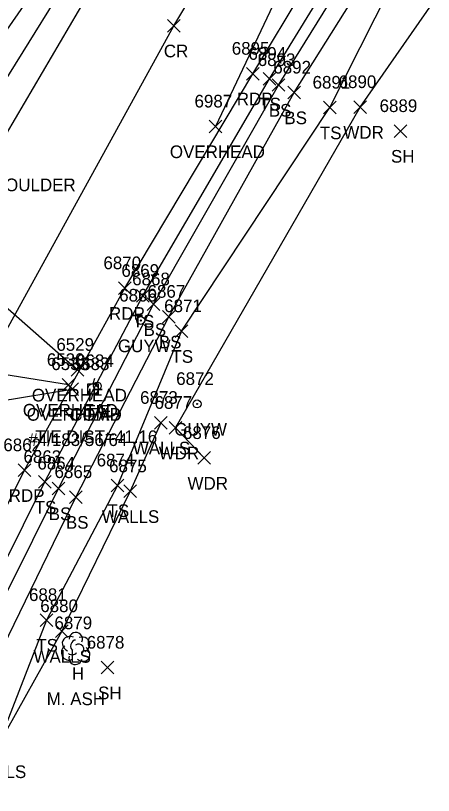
# Model space of a CAD drawing. Extents: x 1611797 to 1633212, y 298978 to 305475.
# Drawn here: x 1623791 to 1623857, y 303824.4 to 303947.6 of the extents above; entities that cross this region are included whole.
import ezdxf

# ---------------------------------------------------------------- set-up
doc = ezdxf.new("R2010")
doc.units = 0
for name, color, linetype in [('C_A', 7, 'Continuous'), ('C_C', 7, 'Continuous'), ('C_I', 7, 'Continuous'), ('CBP', 7, 'Continuous'), ('L_A', 7, 'Continuous'), ('L_C', 7, 'Continuous'), ('L_I', 7, 'Continuous'), ('L_TIC', 7, 'Continuous'), ('LAWA', 7, 'Continuous'), ('LELB', 7, 'Continuous'), ('LTD', 7, 'Continuous'), ('LWS', 7, 'Continuous'), ('P_A', 7, 'Continuous'), ('P_I', 7, 'Continuous'), ('P_TIC', 7, 'Continuous'), ('PET', 7, 'Continuous'), ('PRC', 7, 'Continuous'), ('U_A', 7, 'Continuous'), ('U_C', 7, 'Continuous'), ('U_I', 7, 'Continuous'), ('U_TIC', 7, 'Continuous'), ('UCO', 7, 'Continuous'), ('UP', 7, 'Continuous'), ('UPGW', 7, 'Continuous')]:
    doc.layers.add(name, color=color, linetype=linetype)

msp = doc.modelspace()

# ---------------------------------------------------------------- linework, layer by layer
at = {"layer": 'CBP'}
for radius in [0.625, 0.0833]:
    msp.add_circle((1623803.91, 303889.04), radius, dxfattribs=at)
at = {"layer": 'L_TIC'}
for points in [[(1623830.07, 303936.59), (1623832.07, 303938.59)], [(1623832.07, 303936.59), (1623830.07, 303938.59)], [(1623831.53, 303935.61), (1623833.53, 303937.61)], [(1623833.53, 303935.61), (1623831.53, 303937.61)], [(1623834, 303934.42), (1623836, 303936.42)], [(1623836, 303934.42), (1623834, 303936.42)], [(1623839.63, 303932.04), (1623841.63, 303934.04)], [(1623841.63, 303932.04), (1623839.63, 303934.04)], [(1623839.63, 303932.04), (1623841.63, 303934.04)], [(1623841.63, 303932.04), (1623839.63, 303934.04)], [(1623844.39, 303932.13), (1623846.39, 303934.13)], [(1623846.39, 303932.13), (1623844.39, 303934.13)], [(1623850.79, 303928.34), (1623852.79, 303930.34)], [(1623852.79, 303928.34), (1623850.79, 303930.34)], [(1623810.07, 303902.3), (1623812.07, 303904.3)], [(1623812.07, 303902.3), (1623810.07, 303904.3)], [(1623811.76, 303900.96), (1623813.76, 303902.96)], [(1623813.76, 303900.96), (1623811.76, 303902.96)], [(1623814.19, 303899), (1623816.19, 303901)], [(1623816.19, 303899), (1623814.19, 303901)], [(1623816.2, 303896.72), (1623818.2, 303898.72)], [(1623818.2, 303896.72), (1623816.2, 303898.72)], [(1623816.2, 303896.72), (1623818.2, 303898.72)], [(1623818.2, 303896.72), (1623816.2, 303898.72)], [(1623812.96, 303882.24), (1623814.96, 303884.24)], [(1623814.96, 303882.24), (1623812.96, 303884.24)], [(1623815.25, 303881.45), (1623817.25, 303883.45)], [(1623817.25, 303881.45), (1623815.25, 303883.45)], [(1623819.79, 303876.68), (1623821.79, 303878.68)], [(1623821.79, 303876.68), (1623819.79, 303878.68)], [(1623794.61, 303872.89), (1623796.61, 303874.89)], [(1623796.61, 303872.89), (1623794.61, 303874.89)], [(1623796.8, 303871.86), (1623798.8, 303873.86)], [(1623798.8, 303871.86), (1623796.8, 303873.86)], [(1623806.11, 303872.35), (1623808.11, 303874.35)], [(1623808.11, 303872.35), (1623806.11, 303874.35)], [(1623799.51, 303870.51), (1623801.51, 303872.51)], [(1623801.51, 303870.51), (1623799.51, 303872.51)], [(1623808.08, 303871.42), (1623810.08, 303873.42)], [(1623810.08, 303871.42), (1623808.08, 303873.42)], [(1623794.86, 303851.08), (1623796.86, 303853.08)], [(1623796.86, 303851.08), (1623794.86, 303853.08)], [(1623797.29, 303849.33), (1623799.29, 303851.33)], [(1623799.29, 303849.33), (1623797.29, 303851.33)], [(1623804.54, 303843.56), (1623806.54, 303845.56)], [(1623806.54, 303843.56), (1623804.54, 303845.56)]]:
    msp.add_lwpolyline(points, dxfattribs=at)
at = {"layer": 'LAWA'}
msp.add_lwpolyline([(1623820.79, 303877.68), (1623816.25, 303882.45), (1623845.39, 303933.13), (1623868.52, 303966.33), (1623895.88, 304001.62), (1623916.89, 304037.42), (1623938.51, 304074.19), (1623964.42, 304107.21), (1624004.64, 304144.93), (1624031.16, 304170.25), (1624074.89, 304204.59), (1624093.25, 304225.45), (1624128.84, 304248.67), (1624153.26, 304270.75), (1624186.93, 304294.55), (1624240.75, 304330.36)], dxfattribs=at)
at = {"layer": 'LELB'}
for points in [[(1623740.23, 303740.54), (1623735.95, 303738.13), (1623733.04, 303738.73), (1623730.26, 303741.26), (1623736.66, 303755.3), (1623756.47, 303795.98), (1623775.32, 303833.05), (1623795.61, 303873.89), (1623811.07, 303903.3), (1623831.07, 303937.59), (1623850.6, 303969.47), (1623881.4, 304014.8), (1623901.24, 304044.35), (1623930, 304082.68), (1623952.95, 304110.39), (1623992.55, 304153.19), (1624020.81, 304180.67), (1624058.38, 304214.54), (1624070.13, 304221.5)], [(1623733.78, 303740.47), (1623738.51, 303754.96), (1623759.12, 303794.85), (1623777.54, 303832.17), (1623797.8, 303872.86), (1623812.76, 303901.96), (1623832.53, 303936.61), (1623852.45, 303968.82), (1623883.01, 304013.7), (1623903, 304043.14), (1623931.54, 304080.8), (1623954.14, 304109.34), (1623993.44, 304152.2), (1624022.26, 304179.45), (1624060.69, 304212.27), (1624070.13, 304220.57)], [(1623733.78, 303740.47), (1623735.41, 303740.12), (1623741.31, 303753.52), (1623763.42, 303793.2), (1623780.16, 303829.64), (1623800.51, 303871.51), (1623815.19, 303900), (1623835, 303935.42), (1623854.96, 303967.29), (1623885.08, 304011.89), (1623905.91, 304041.32), (1623933.42, 304079.65), (1623956.31, 304107.74), (1623995.39, 304150.94), (1624023.82, 304177.46), (1624061.85, 304211.18), (1624071.01, 304219.63), (1624070.13, 304220.57)], [(1623840.63, 303933.04), (1623857.36, 303966.24), (1623887.8, 304009.35), (1623908, 304039.91), (1623936.29, 304076.6), (1623958.73, 304105.76), (1623997.87, 304149.47), (1624026.32, 304175.43), (1624063.15, 304209.38), (1624073.81, 304217.48), (1624072.56, 304218.74)], [(1623716.05, 303912.02), (1623732.35, 303913.81), (1623759.04, 303912.24), (1623771.78, 303913.97), (1623774.93, 303915.99), (1623779.73, 303921.83), (1623800.29, 303954.97), (1623820.51, 303988.09), (1623840.34, 304020.02), (1623836.12, 304025.99), (1623832.01, 304025.34)], [(1623817.2, 303897.72), (1623840.63, 303933.04)], [(1623817.2, 303897.72), (1623807.11, 303873.35), (1623795.86, 303852.08), (1623788.08, 303832.11), (1623776.41, 303807.67), (1623761.8, 303779.72), (1623754.87, 303764.43)]]:
    msp.add_lwpolyline(points, dxfattribs=at)
at = {"layer": 'LTD'}
msp.add_line((1623800.46, 303847.63), (1623800.46, 303847.63), dxfattribs=at)
msp.add_line((1623800.46, 303847.63), (1623800.46, 303847.63), dxfattribs=at)
msp.add_arc((1623800.51, 303849.06), 1.05, 335.5272, 180.9563, dxfattribs=at)
for centre, major_axis, ratio, start_param, end_param in [((1623799.67, 303848.29), (1.21, -0.51), 0.895232, 1.570796, 4.712389), ((1623801.5, 303848.21), (-1.14, -0.48), 0.949671, 1.570796, 4.712389), ((1623799.38, 303846.92), (0.58, -1.04), 0.959034, 3.141593, 6.283185), ((1623800.25, 303848.09), (-0.208, -0.792), 0.645439, 3.141593, 6.283185), ((1623800.96, 303847.46), (-0.5, 0.667), 0.989748, 3.141593, 6.283185), ((1623800, 303846.88), (-0.625, -0.083), 0.423636, 0, 3.141593), ((1623801.46, 303846.8), (-1.09, 0.79), 0.841452, 1.570796, 4.712389), ((1623800.46, 303846.13), (0.26, 1.06), 0.942809, 1.570796, 4.712389)]:
    msp.add_ellipse(centre, major_axis=major_axis, ratio=ratio, start_param=start_param, end_param=end_param, dxfattribs=at)
at = {"layer": 'LWS'}
for points in [[(1623717.19, 303914.78), (1623732.04, 303916.68), (1623760.06, 303916.18), (1623770.53, 303917.84), (1623797.52, 303956.71), (1623816.42, 303989.59), (1623837.84, 304021.99)], [(1623813.96, 303883.24), (1623809.08, 303872.42), (1623798.29, 303850.33), (1623788.08, 303832.11)]]:
    msp.add_lwpolyline(points, dxfattribs=at)
at = {"layer": 'P_TIC'}
for points in [[(1623814.97, 303944.98), (1623816.97, 303946.98)], [(1623816.97, 303944.98), (1623814.97, 303946.98)], [(1623827.44, 303937.4), (1623829.44, 303939.4)], [(1623829.44, 303937.4), (1623827.44, 303939.4)], [(1623807.26, 303903.51), (1623809.26, 303905.51)], [(1623809.26, 303903.51), (1623807.26, 303905.51)], [(1623791.43, 303874.75), (1623793.43, 303876.75)], [(1623793.43, 303874.75), (1623791.43, 303876.75)]]:
    msp.add_lwpolyline(points, dxfattribs=at)
at = {"layer": 'PET'}
for points in [[(1623734.72, 303818.72), (1623741.35, 303832.79), (1623751.88, 303855.21), (1623768.06, 303888.23), (1623783.81, 303919.21), (1623803.8, 303953.17), (1623823.4, 303986.78), (1623844.63, 304021.43), (1623861.98, 304047.29), (1623874.41, 304064.9), (1623903.88, 304103.57), (1623926.42, 304130.92), (1623968.84, 304177.26), (1623998.66, 304205.49), (1624036.82, 304239.77), (1624084.71, 304279.03), (1624112.56, 304299.92), (1624120.23, 304305.61), (1624165.06, 304338.25), (1624214.6, 304372.95), (1624258.69, 304401.17)], [(1623753.98, 303796.37), (1623772.12, 303834.51), (1623792.43, 303875.75), (1623808.26, 303904.51), (1623828.44, 303938.4), (1623847.99, 303970.88), (1623878.6, 304016.89), (1623898.4, 304046.12), (1623927.58, 304084.75), (1623950.31, 304112.67), (1623990.12, 304155.59), (1624018.08, 304183.31), (1624056.52, 304216.58), (1624078.27, 304234.86), (1624102.63, 304254.08), (1624138.53, 304281.62), (1624179.36, 304312.24), (1624229.96, 304347.62)]]:
    msp.add_lwpolyline(points, dxfattribs=at)
at = {"layer": 'PRC'}
msp.add_lwpolyline([(1623741.55, 303802.02), (1623760.52, 303841.05), (1623780.51, 303881.51), (1623815.97, 303945.98), (1623835.49, 303978.53), (1623866.25, 304025.48), (1623886.62, 304054.99), (1623916.18, 304093.56), (1623939.04, 304122.75), (1623980.27, 304165.88), (1624008.94, 304194.69), (1624046.78, 304227.75), (1624094.29, 304266.19), (1624129.15, 304293.39), (1624172.24, 304325.39), (1624222.29, 304360.15)], dxfattribs=at)
at = {"layer": 'U_TIC'}
for points in [[(1623821.55, 303929.06), (1623823.55, 303931.06)], [(1623823.55, 303929.06), (1623821.55, 303931.06)], [(1623799.76, 303890.61), (1623801.76, 303892.61)], [(1623801.76, 303890.61), (1623799.76, 303892.61)], [(1623798.34, 303888.22), (1623800.34, 303890.22)], [(1623800.34, 303888.22), (1623798.34, 303890.22)], [(1623798.95, 303887.57), (1623800.95, 303889.57)], [(1623800.95, 303887.57), (1623798.95, 303889.57)]]:
    msp.add_lwpolyline(points, dxfattribs=at)
at = {"layer": 'UCO'}
for points in [[(1623903.55, 304101.16), (1623822.55, 303930.06)], [(1623777.93, 303911.67), (1623800.76, 303891.61)], [(1623799.34, 303889.22), (1623759.47, 303895.61)], [(1623749.63, 303880.28), (1623799.95, 303888.57)]]:
    msp.add_lwpolyline(points, dxfattribs=at)
at = {"layer": 'UP'}
for p, q in [((1623803.47, 303890.24), (1623803.22, 303889.41)), ((1623802.39, 303887.74), (1623802.39, 303889.41)), ((1623802.39, 303889.41), (1623804.05, 303889.41)), ((1623803.22, 303888.57), (1623803.22, 303888.57)), ((1623804.05, 303889.41), (1623804.05, 303887.74)), ((1623804.05, 303887.74), (1623802.39, 303887.74)), ((1623802.97, 303886.91), (1623803.22, 303887.74))]:
    msp.add_line(p, q, dxfattribs=at)
msp.add_circle((1623803.22, 303888.57), 0.833, dxfattribs=at)
at = {"layer": 'UPGW'}
for centre, radius in [((1623810.77, 303899.4), 0.625), ((1623810.77, 303899.4), 0.0833), ((1623819.66, 303886.22), 0.625), ((1623819.66, 303886.22), 0.0833)]:
    msp.add_circle(centre, radius, dxfattribs=at)

# ---------------------------------------------------------------- texts
at = {"layer": 'C_A'}
msp.add_text('TIE', height=2, dxfattribs=at).set_placement((1623801.98, 303884.04))
at = {"layer": 'C_C'}
for s, p in [('CHISELED SQUARE ON BOULDER', (1623756.65, 303919.83)), ('TIE DIST=41.16', (1623794.12, 303880.04))]:
    msp.add_text(s, height=2, dxfattribs=at).set_placement(p)
at = {"layer": 'C_I'}
msp.add_text('6684', height=2, dxfattribs=at).set_placement((1623800.55, 303892.04))
at = {"layer": 'L_A'}
for s, p in [('TS', (1623829.48, 303932.59)), ('BS', (1623830.98, 303931.61)), ('BS', (1623833.44, 303930.42)), ('TS', (1623839.04, 303928.04)), ('TS', (1623839.04, 303928.04)), ('WDR', (1623842.75, 303928.13)), ('SH', (1623850.27, 303924.34)), ('TS', (1623809.48, 303898.3)), ('BS', (1623811.21, 303896.96)), ('BS', (1623813.63, 303895)), ('TS', (1623815.61, 303892.72)), ('TS', (1623815.61, 303892.72)), ('WALLS', (1623809.51, 303878.24)), ('WDR', (1623813.61, 303877.45)), ('WDR', (1623818.15, 303872.68)), ('TS', (1623794.02, 303868.89)), ('TS', (1623805.52, 303868.35)), ('BS', (1623796.24, 303867.86)), ('WALLS', (1623804.62, 303867.42)), ('BS', (1623798.95, 303866.51)), ('TS', (1623794.27, 303847.08)), ('WALLS', (1623793.83, 303845.33)), ('H', (1623799.89, 303842.63)), ('SH', (1623804.03, 303839.56)), ('WALLS', (1623783.62, 303827.11))]:
    msp.add_text(s, height=2, dxfattribs=at).set_placement(p)
at = {"layer": 'L_C'}
msp.add_text('M. ASH', height=2, dxfattribs=at).set_placement((1623795.92, 303838.63))
at = {"layer": 'L_I'}
for s, p in [('6894', (1623827.77, 303940.59)), ('6893', (1623829.23, 303939.61)), ('6892', (1623831.69, 303938.42)), ('6891', (1623837.89, 303936.04)), ('6891', (1623837.89, 303936.04)), ('6890', (1623842, 303936.13)), ('6889', (1623848.47, 303932.34)), ('6869', (1623807.71, 303906.3)), ('6868', (1623809.41, 303904.96)), ('6867', (1623811.84, 303903)), ('6871', (1623814.46, 303900.72)), ('6871', (1623814.46, 303900.72)), ('6873', (1623810.66, 303886.24)), ('6877', (1623812.94, 303885.45)), ('6876', (1623817.43, 303880.68)), ('6863', (1623792.25, 303876.89)), ('6864', (1623794.44, 303875.86)), ('6874', (1623803.8, 303876.35)), ('6875', (1623805.77, 303875.42)), ('6865', (1623797.15, 303874.51)), ('6881', (1623793.12, 303855.08)), ('6880', (1623794.9, 303853.33)), ('6879', (1623797.14, 303850.63)), ('6878', (1623802.23, 303847.56))]:
    msp.add_text(s, height=2, dxfattribs=at).set_placement(p)
at = {"layer": 'P_A'}
for s, p in [('CR', (1623814.41, 303940.98)), ('RDP', (1623825.93, 303933.4)), ('RDP', (1623805.75, 303899.51)), ('RDP', (1623789.92, 303870.75))]:
    msp.add_text(s, height=2, dxfattribs=at).set_placement(p)
at = {"layer": 'P_I'}
for s, p in [('6895', (1623825.13, 303941.4)), ('6870', (1623804.87, 303907.51)), ('6862', (1623789.07, 303878.75))]:
    msp.add_text(s, height=2, dxfattribs=at).set_placement(p)
at = {"layer": 'U_A'}
for s, p in [('OVERHEAD', (1623815.36, 303925.06)), ('GUYW', (1623807.16, 303894.4)), ('OVERHEAD', (1623793.57, 303886.61)), ('OVERHEAD', (1623792.15, 303884.22)), ('OVERHEAD', (1623792.76, 303883.57)), ('COMB', (1623799.61, 303883.57)), ('GUYW', (1623816.06, 303881.22))]:
    msp.add_text(s, height=2, dxfattribs=at).set_placement(p)
at = {"layer": 'U_C'}
msp.add_text('#4/183/56/64', height=2, dxfattribs=at).set_placement((1623793.02, 303879.57))
at = {"layer": 'U_I'}
for s, p in [('6987', (1623819.25, 303933.06)), ('6866', (1623807.36, 303902.4)), ('6529', (1623797.44, 303894.61)), ('6530', (1623795.94, 303892.22)), ('6533', (1623796.64, 303891.57)), ('6683', (1623799.87, 303891.57)), ('6872', (1623816.36, 303889.22))]:
    msp.add_text(s, height=2, dxfattribs=at).set_placement(p)

doc.saveas('drawing.dxf')
